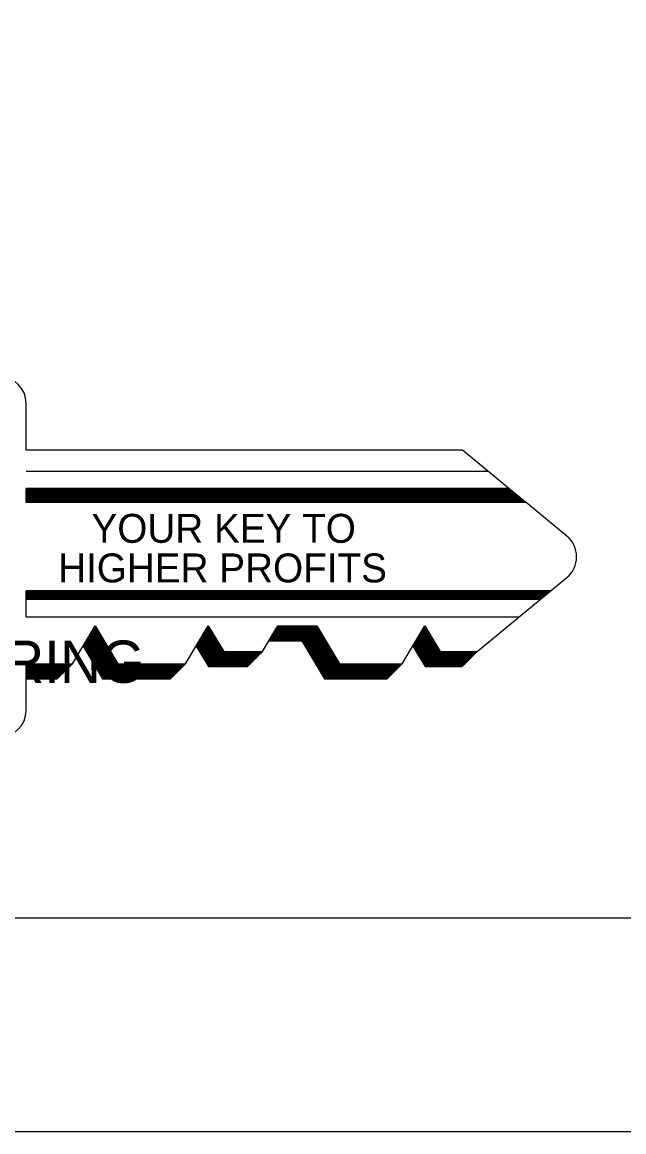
# Model space of a CAD drawing. Extents: x 4.9 to 31.6, y 3.9 to 22.6.
# Drawn here: x 6.8 to 7.739, y 3.926 to 5.658 of the extents above; entities that cross this region are included whole.
import ezdxf

# ---------------------------------------------------------------- set-up
doc = ezdxf.new("R2010")
doc.units = 0
doc.layers.add('Level 1', color=7, linetype='Continuous')

msp = doc.modelspace()

# ---------------------------------------------------------------- linework, layer by layer
at = {"layer": 'Level 1'}
for p, q in [((6.8065, 4.9899), (6.8065, 5.0628)), ((7.4872, 4.9899), (6.8065, 4.9899)), ((7.5859, 4.9082), (7.4874, 4.9899)), ((7.5275, 4.9565), (6.8065, 4.9565)), ((6.8065, 4.908), (6.8065, 4.9297)), ((7.5599, 4.9297), (6.8065, 4.9297)), ((7.5606, 4.9292), (6.8065, 4.9292)), ((7.5612, 4.9287), (6.8065, 4.9287)), ((7.5619, 4.9281), (6.8065, 4.9281)), ((7.5626, 4.9275), (6.8065, 4.9275)), ((7.5633, 4.927), (6.8065, 4.927)), ((7.5641, 4.9263), (6.8065, 4.9263)), ((7.5648, 4.9257), (6.8065, 4.9257)), ((7.5656, 4.925), (6.8065, 4.925)), ((7.5664, 4.9244), (6.8065, 4.9244)), ((7.5671, 4.9238), (6.8065, 4.9238)), ((7.5679, 4.9231), (6.8065, 4.9231)), ((7.5688, 4.9225), (6.8065, 4.9225)), ((7.5694, 4.9219), (6.8065, 4.9219)), ((7.5701, 4.9213), (6.8065, 4.9213)), ((7.5709, 4.9206), (6.8065, 4.9206)), ((7.5718, 4.92), (6.8065, 4.92)), ((7.5725, 4.9193), (6.8065, 4.9193)), ((7.5734, 4.9185), (6.8065, 4.9185)), ((7.5742, 4.918), (6.8065, 4.918)), ((7.5677, 4.9233), (7.5674, 4.9235)), ((7.5681, 4.923), (7.5677, 4.9233)), ((7.5707, 4.9208), (7.5681, 4.923)), ((7.5719, 4.9199), (7.5707, 4.9208)), ((7.5749, 4.9173), (6.8065, 4.9173)), ((7.5759, 4.9165), (6.8065, 4.9165)), ((7.5767, 4.9159), (6.8065, 4.9159)), ((7.5773, 4.9154), (6.8065, 4.9154)), ((7.5781, 4.9147), (6.8065, 4.9147)), ((7.5789, 4.914), (6.8065, 4.914)), ((7.5796, 4.9135), (6.8065, 4.9135)), ((7.5803, 4.9129), (6.8065, 4.9129)), ((7.5809, 4.9124), (6.8065, 4.9124)), ((7.5819, 4.9116), (6.8065, 4.9116)), ((7.5824, 4.9111), (6.8065, 4.9111)), ((7.5831, 4.9105), (6.8065, 4.9105)), ((7.5837, 4.91), (6.8065, 4.91)), ((7.5844, 4.9095), (6.8065, 4.9095)), ((7.5849, 4.9091), (6.8065, 4.9091)), ((7.5854, 4.9086), (6.8065, 4.9086)), ((7.5859, 4.9083), (6.8065, 4.9083)), ((7.5863, 4.908), (6.8065, 4.908)), ((7.5863, 4.908), (7.5859, 4.9082)), ((7.65, 4.8553), (7.5863, 4.908)), ((7.5102, 4.6755), (7.65, 4.7911)), ((7.6249, 4.7703), (6.8065, 4.7703)), ((6.8065, 4.729), (6.8065, 4.7703)), ((7.6235, 4.7692), (6.8065, 4.7692)), ((7.6221, 4.768), (6.8065, 4.768)), ((7.6205, 4.7667), (6.8065, 4.7667)), ((7.6192, 4.7656), (6.8065, 4.7656)), ((7.6176, 4.7643), (6.8065, 4.7643)), ((7.6162, 4.7631), (6.8065, 4.7631)), ((7.6147, 4.7619), (6.8065, 4.7619)), ((7.613, 4.7605), (6.8065, 4.7605)), ((7.6115, 4.7593), (6.8065, 4.7593)), ((7.6101, 4.7581), (6.8065, 4.7581)), ((7.6091, 4.7573), (6.8065, 4.7573)), ((7.6082, 4.7565), (6.8065, 4.7565)), ((7.5749, 4.729), (6.8065, 4.729)), ((6.8788, 4.6565), (6.9142, 4.7156)), ((6.9109, 4.7101), (6.9174, 4.7101)), ((6.9113, 4.7108), (6.9171, 4.7108)), ((6.9117, 4.7115), (6.9167, 4.7115)), ((6.9121, 4.7121), (6.9163, 4.7121)), ((6.9125, 4.7128), (6.9159, 4.7128)), ((6.9129, 4.7135), (6.9155, 4.7135)), ((6.9133, 4.7141), (6.9151, 4.7141)), ((6.9137, 4.7148), (6.9147, 4.7148)), ((6.9142, 4.7156), (6.9495, 4.6565)), ((7.0554, 4.6565), (7.0907, 4.7156)), ((7.0874, 4.7101), (7.0939, 4.7101)), ((7.0878, 4.7108), (7.0936, 4.7108)), ((7.0882, 4.7115), (7.0932, 4.7115)), ((7.0886, 4.7121), (7.0928, 4.7121)), ((7.089, 4.7128), (7.0924, 4.7128)), ((7.0894, 4.7135), (7.092, 4.7135)), ((7.0897, 4.714), (7.0917, 4.714)), ((7.09, 4.7145), (7.0914, 4.7145)), ((7.0903, 4.715), (7.0911, 4.715)), ((7.0907, 4.7156), (7.1148, 4.6755)), ((7.1754, 4.6755), (7.1994, 4.7156)), ((7.1961, 4.7101), (7.2634, 4.7101)), ((7.1965, 4.7108), (7.263, 4.7108)), ((7.1969, 4.7115), (7.2626, 4.7115)), ((7.1974, 4.7121), (7.2622, 4.7121)), ((7.1978, 4.7128), (7.2618, 4.7128)), ((7.1981, 4.7134), (7.2614, 4.7134)), ((7.1984, 4.714), (7.2611, 4.714)), ((7.1988, 4.7145), (7.2608, 4.7145)), ((7.1991, 4.715), (7.2604, 4.715)), ((7.1994, 4.7156), (7.2601, 4.7156)), ((7.2601, 4.7156), (7.2955, 4.6565)), ((7.3932, 4.6565), (7.4286, 4.7156)), ((7.4253, 4.7101), (7.4319, 4.7101)), ((7.4257, 4.7108), (7.4315, 4.7108)), ((7.4261, 4.7115), (7.4311, 4.7115)), ((7.4265, 4.7121), (7.4307, 4.7121)), ((7.4269, 4.7128), (7.4303, 4.7128)), ((7.4273, 4.7135), (7.4299, 4.7135)), ((7.4276, 4.714), (7.4296, 4.714)), ((7.4286, 4.7156), (7.4526, 4.6755)), ((6.9006, 4.6928), (6.9279, 4.6928)), ((6.901, 4.6935), (6.9274, 4.6935)), ((6.9014, 4.6941), (6.927, 4.6941)), ((6.9019, 4.6948), (6.9267, 4.6948)), ((6.9021, 4.6955), (6.9263, 4.6955)), ((6.9025, 4.6961), (6.9259, 4.6961)), ((6.9029, 4.6968), (6.9254, 4.6968)), ((6.9033, 4.6975), (6.925, 4.6975)), ((6.9037, 4.6981), (6.9247, 4.6981)), ((6.9041, 4.6988), (6.9243, 4.6988)), ((6.9045, 4.6995), (6.9239, 4.6995)), ((6.9049, 4.7001), (6.9234, 4.7001)), ((6.9053, 4.7008), (6.923, 4.7008)), ((6.9057, 4.7015), (6.9227, 4.7015)), ((6.9061, 4.7021), (6.9223, 4.7021)), ((6.9065, 4.7028), (6.9219, 4.7028)), ((6.9069, 4.7035), (6.9214, 4.7035)), ((6.9074, 4.7041), (6.9211, 4.7041)), ((6.9078, 4.7048), (6.9207, 4.7048)), ((6.9082, 4.7055), (6.9203, 4.7055)), ((6.9086, 4.7061), (6.9199, 4.7061)), ((6.9089, 4.7068), (6.9194, 4.7068)), ((6.9093, 4.7075), (6.9191, 4.7075)), ((6.9097, 4.7081), (6.9187, 4.7081)), ((6.9101, 4.7088), (6.9183, 4.7088)), ((6.9105, 4.7095), (6.9179, 4.7095)), ((7.0771, 4.6928), (7.1044, 4.6928)), ((7.0775, 4.6935), (7.1039, 4.6935)), ((7.0779, 4.6941), (7.1035, 4.6941)), ((7.0784, 4.6948), (7.1032, 4.6948)), ((7.0786, 4.6955), (7.1028, 4.6955)), ((7.079, 4.6961), (7.1024, 4.6961)), ((7.0794, 4.6968), (7.1019, 4.6968)), ((7.0798, 4.6975), (7.1015, 4.6975)), ((7.0802, 4.6981), (7.1012, 4.6981)), ((7.0806, 4.6988), (7.1008, 4.6988)), ((7.081, 4.6995), (7.1004, 4.6995)), ((7.0814, 4.7001), (7.0999, 4.7001)), ((7.0818, 4.7008), (7.0995, 4.7008)), ((7.0822, 4.7015), (7.0992, 4.7015)), ((7.0826, 4.7021), (7.0988, 4.7021)), ((7.083, 4.7028), (7.0984, 4.7028)), ((7.0834, 4.7035), (7.0979, 4.7035)), ((7.0839, 4.7041), (7.0976, 4.7041)), ((7.0843, 4.7048), (7.0972, 4.7048)), ((7.0847, 4.7055), (7.0968, 4.7055)), ((7.0851, 4.7061), (7.0964, 4.7061)), ((7.0854, 4.7068), (7.0959, 4.7068)), ((7.0858, 4.7075), (7.0956, 4.7075)), ((7.0862, 4.7081), (7.0952, 4.7081)), ((7.0866, 4.7088), (7.0948, 4.7088)), ((7.087, 4.7095), (7.0944, 4.7095)), ((7.1858, 4.6928), (7.2738, 4.6928)), ((7.1862, 4.6935), (7.2734, 4.6935)), ((7.1866, 4.6941), (7.2729, 4.6941)), ((7.1869, 4.6948), (7.2726, 4.6948)), ((7.1874, 4.6955), (7.2722, 4.6955)), ((7.1878, 4.6961), (7.2718, 4.6961)), ((7.1882, 4.6968), (7.2714, 4.6968)), ((7.1885, 4.6975), (7.2709, 4.6975)), ((7.1889, 4.6981), (7.2706, 4.6981)), ((7.1894, 4.6988), (7.2702, 4.6988)), ((7.1898, 4.6995), (7.2698, 4.6995)), ((7.1902, 4.7001), (7.2694, 4.7001)), ((7.1905, 4.7008), (7.2689, 4.7008)), ((7.1909, 4.7015), (7.2686, 4.7015)), ((7.1914, 4.7021), (7.2682, 4.7021)), ((7.1918, 4.7028), (7.2678, 4.7028)), ((7.1922, 4.7035), (7.2674, 4.7035)), ((7.1925, 4.7041), (7.267, 4.7041)), ((7.1929, 4.7048), (7.2666, 4.7048)), ((7.1934, 4.7055), (7.2662, 4.7055)), ((7.1938, 4.7061), (7.2658, 4.7061)), ((7.1942, 4.7068), (7.2654, 4.7068)), ((7.1945, 4.7075), (7.265, 4.7075)), ((7.1949, 4.7081), (7.2646, 4.7081)), ((7.1954, 4.7088), (7.2642, 4.7088)), ((7.1958, 4.7095), (7.2638, 4.7095)), ((7.415, 4.6928), (7.4423, 4.6928)), ((7.4154, 4.6935), (7.4419, 4.6935)), ((7.4159, 4.6941), (7.4414, 4.6941)), ((7.4163, 4.6948), (7.4411, 4.6948)), ((7.4165, 4.6955), (7.4407, 4.6955)), ((7.4169, 4.6961), (7.4403, 4.6961)), ((7.4174, 4.6968), (7.4399, 4.6968)), ((7.4177, 4.6975), (7.4394, 4.6975)), ((7.4181, 4.6981), (7.4391, 4.6981)), ((7.4185, 4.6988), (7.4387, 4.6988)), ((7.4189, 4.6995), (7.4383, 4.6995)), ((7.4194, 4.7001), (7.4379, 4.7001)), ((7.4197, 4.7008), (7.4374, 4.7008)), ((7.4201, 4.7015), (7.4371, 4.7015)), ((7.4205, 4.7021), (7.4367, 4.7021)), ((7.4209, 4.7028), (7.4363, 4.7028)), ((7.4214, 4.7035), (7.4359, 4.7035)), ((7.4218, 4.7041), (7.4355, 4.7041)), ((7.4222, 4.7048), (7.4351, 4.7048)), ((7.4226, 4.7055), (7.4347, 4.7055)), ((7.423, 4.7061), (7.4343, 4.7061)), ((7.4233, 4.7068), (7.4339, 4.7068)), ((7.4237, 4.7075), (7.4335, 4.7075)), ((7.4241, 4.7081), (7.4331, 4.7081)), ((7.4245, 4.7088), (7.4327, 4.7088)), ((7.4249, 4.7095), (7.4323, 4.7095)), ((6.8954, 4.6841), (6.9259, 4.633)), ((6.8954, 4.6841), (6.933, 4.6841)), ((6.8957, 4.6848), (6.9326, 4.6848)), ((6.8958, 4.6835), (6.9334, 4.6835)), ((6.8961, 4.6855), (6.9322, 4.6855)), ((6.8962, 4.6828), (6.9339, 4.6828)), ((6.8965, 4.6861), (6.9319, 4.6861)), ((6.8965, 4.6821), (6.9342, 4.6821)), ((6.8969, 4.6868), (6.9314, 4.6868)), ((6.8969, 4.6815), (6.9346, 4.6815)), ((6.8973, 4.6875), (6.931, 4.6875)), ((6.8974, 4.6808), (6.9349, 4.6808)), ((6.8977, 4.6881), (6.9306, 4.6881)), ((6.8978, 4.6801), (6.9353, 4.6801)), ((6.8981, 4.6888), (6.9303, 4.6888)), ((6.8981, 4.6795), (6.9357, 4.6795)), ((6.8985, 4.6895), (6.9299, 4.6895)), ((6.8985, 4.6788), (6.9361, 4.6788)), ((6.8989, 4.6901), (6.9294, 4.6901)), ((6.8989, 4.6781), (6.9365, 4.6781)), ((6.8994, 4.6908), (6.929, 4.6908)), ((6.8994, 4.6775), (6.9369, 4.6775)), ((6.8998, 4.6915), (6.9286, 4.6915)), ((6.8998, 4.6768), (6.9374, 4.6768)), ((6.9001, 4.6761), (6.9378, 4.6761)), ((6.9002, 4.6921), (6.9283, 4.6921)), ((6.9005, 4.6755), (6.9382, 4.6755)), ((7.0719, 4.6841), (7.0912, 4.652)), ((7.0719, 4.6841), (7.1095, 4.6841)), ((7.0722, 4.6848), (7.1091, 4.6848)), ((7.0723, 4.6835), (7.1099, 4.6835)), ((7.0726, 4.6855), (7.1087, 4.6855)), ((7.0727, 4.6828), (7.1104, 4.6828)), ((7.073, 4.6861), (7.1084, 4.6861)), ((7.073, 4.6821), (7.1107, 4.6821)), ((7.0734, 4.6868), (7.1079, 4.6868)), ((7.0734, 4.6815), (7.1111, 4.6815)), ((7.0738, 4.6875), (7.1075, 4.6875)), ((7.0739, 4.6808), (7.1114, 4.6808)), ((7.0742, 4.6881), (7.1071, 4.6881)), ((7.0743, 4.6801), (7.1118, 4.6801)), ((7.0746, 4.6888), (7.1068, 4.6888)), ((7.0746, 4.6795), (7.1122, 4.6795)), ((7.075, 4.6895), (7.1064, 4.6895)), ((7.075, 4.6788), (7.1126, 4.6788)), ((7.0754, 4.6901), (7.1059, 4.6901)), ((7.0754, 4.6781), (7.113, 4.6781)), ((7.0759, 4.6908), (7.1055, 4.6908)), ((7.0759, 4.6775), (7.1134, 4.6775)), ((7.0763, 4.6915), (7.1051, 4.6915)), ((7.0763, 4.6768), (7.1139, 4.6768)), ((7.0766, 4.6761), (7.1143, 4.6761)), ((7.0767, 4.6921), (7.1048, 4.6921)), ((7.077, 4.6755), (7.1147, 4.6755)), ((7.1148, 4.6755), (7.1754, 4.6755)), ((7.1519, 4.652), (7.1754, 4.6755)), ((7.1854, 4.6921), (7.2742, 4.6921)), ((7.1854, 4.692), (7.2365, 4.692)), ((7.2365, 4.692), (7.2719, 4.633)), ((7.2369, 4.6915), (7.2745, 4.6915)), ((7.2373, 4.6908), (7.2749, 4.6908)), ((7.2377, 4.6901), (7.2754, 4.6901)), ((7.2381, 4.6895), (7.2758, 4.6895)), ((7.2384, 4.6888), (7.2762, 4.6888)), ((7.2389, 4.6881), (7.2765, 4.6881)), ((7.2393, 4.6875), (7.2769, 4.6875)), ((7.2397, 4.6868), (7.2774, 4.6868)), ((7.2401, 4.6861), (7.2778, 4.6861)), ((7.2404, 4.6855), (7.2781, 4.6855)), ((7.2409, 4.6848), (7.2785, 4.6848)), ((7.2413, 4.6841), (7.2789, 4.6841)), ((7.2417, 4.6835), (7.2794, 4.6835)), ((7.2421, 4.6828), (7.2798, 4.6828)), ((7.2424, 4.6821), (7.2801, 4.6821)), ((7.2429, 4.6815), (7.2805, 4.6815)), ((7.2433, 4.6808), (7.2808, 4.6808)), ((7.2437, 4.6801), (7.2812, 4.6801)), ((7.244, 4.6795), (7.2816, 4.6795)), ((7.2444, 4.6788), (7.282, 4.6788)), ((7.2449, 4.6781), (7.2824, 4.6781)), ((7.2453, 4.6775), (7.2829, 4.6775)), ((7.2457, 4.6768), (7.2833, 4.6768)), ((7.246, 4.6761), (7.2837, 4.6761)), ((7.2464, 4.6755), (7.2841, 4.6755)), ((7.4098, 4.6841), (7.429, 4.652)), ((7.4098, 4.6841), (7.4474, 4.6841)), ((7.4101, 4.6848), (7.447, 4.6848)), ((7.4102, 4.6835), (7.4479, 4.6835)), ((7.4105, 4.6855), (7.4466, 4.6855)), ((7.4106, 4.6828), (7.4483, 4.6828)), ((7.4109, 4.6861), (7.4463, 4.6861)), ((7.4109, 4.6821), (7.4486, 4.6821)), ((7.4114, 4.6868), (7.4459, 4.6868)), ((7.4114, 4.6815), (7.449, 4.6815)), ((7.4117, 4.6875), (7.4454, 4.6875)), ((7.4118, 4.6808), (7.4493, 4.6808)), ((7.4121, 4.6881), (7.445, 4.6881)), ((7.4122, 4.6801), (7.4497, 4.6801)), ((7.4125, 4.6888), (7.4447, 4.6888)), ((7.4125, 4.6795), (7.4501, 4.6795)), ((7.4129, 4.6895), (7.4443, 4.6895)), ((7.4129, 4.6788), (7.4505, 4.6788)), ((7.4134, 4.6901), (7.4439, 4.6901)), ((7.4134, 4.6781), (7.4509, 4.6781)), ((7.4138, 4.6908), (7.4434, 4.6908)), ((7.4138, 4.6775), (7.4514, 4.6775)), ((7.4142, 4.6915), (7.443, 4.6915)), ((7.4142, 4.6768), (7.4518, 4.6768)), ((7.4145, 4.6761), (7.4522, 4.6761)), ((7.4146, 4.6921), (7.4427, 4.6921)), ((7.4149, 4.6755), (7.4526, 4.6755)), ((7.4526, 4.6755), (7.5102, 4.6755)), ((7.4866, 4.652), (7.5102, 4.6755)), ((6.9009, 4.6748), (6.9386, 4.6748)), ((6.9013, 4.6743), (6.9389, 4.6743)), ((6.9016, 4.6736), (6.9393, 4.6736)), ((6.902, 4.673), (6.9397, 4.673)), ((6.9024, 4.6722), (6.9402, 4.6722)), ((6.9029, 4.6714), (6.9407, 4.6714)), ((6.9034, 4.6706), (6.9411, 4.6706)), ((6.9039, 4.6697), (6.9417, 4.6697)), ((6.9044, 4.6689), (6.9421, 4.6689)), ((6.9051, 4.6679), (6.9428, 4.6679)), ((6.9056, 4.667), (6.9433, 4.667)), ((6.9062, 4.666), (6.9439, 4.666)), ((6.9068, 4.665), (6.9445, 4.665)), ((6.9073, 4.6641), (6.945, 4.6641)), ((6.9078, 4.6633), (6.9455, 4.6633)), ((6.9084, 4.6623), (6.9461, 4.6623)), ((6.9089, 4.6614), (6.9466, 4.6614)), ((6.9095, 4.6604), (6.9472, 4.6604)), ((6.9104, 4.659), (6.948, 4.659)), ((6.911, 4.658), (6.9487, 4.658)), ((7.0774, 4.6748), (7.1151, 4.6748)), ((7.0778, 4.6743), (7.1154, 4.6743)), ((7.0781, 4.6736), (7.1158, 4.6736)), ((7.0785, 4.673), (7.1162, 4.673)), ((7.0789, 4.6722), (7.1167, 4.6722)), ((7.0794, 4.6714), (7.1172, 4.6714)), ((7.0799, 4.6706), (7.1176, 4.6706)), ((7.0802, 4.6703), (7.1702, 4.6703)), ((7.0808, 4.6693), (7.1692, 4.6693)), ((7.0814, 4.6683), (7.1682, 4.6683)), ((7.0819, 4.6674), (7.1673, 4.6674)), ((7.0825, 4.6664), (7.1663, 4.6664)), ((7.0831, 4.6654), (7.1653, 4.6654)), ((7.0837, 4.6644), (7.1643, 4.6644)), ((7.0844, 4.6634), (7.1633, 4.6634)), ((7.0847, 4.6627), (7.1626, 4.6627)), ((7.0852, 4.662), (7.1619, 4.662)), ((7.0858, 4.661), (7.1609, 4.661)), ((7.0864, 4.66), (7.1599, 4.66)), ((7.0869, 4.6591), (7.159, 4.6591)), ((7.0875, 4.658), (7.1579, 4.658)), ((7.1032, 4.6747), (7.1746, 4.6747)), ((7.1032, 4.674), (7.1739, 4.674)), ((7.1032, 4.6732), (7.1731, 4.6732)), ((7.1032, 4.6723), (7.1722, 4.6723)), ((7.1032, 4.6714), (7.1713, 4.6714)), ((7.2469, 4.6748), (7.2845, 4.6748)), ((7.2472, 4.6743), (7.2849, 4.6743)), ((7.2475, 4.6736), (7.2852, 4.6736)), ((7.2479, 4.673), (7.2856, 4.673)), ((7.2484, 4.6722), (7.2861, 4.6722)), ((7.2489, 4.6714), (7.2866, 4.6714)), ((7.2494, 4.6706), (7.287, 4.6706)), ((7.2499, 4.6697), (7.2876, 4.6697)), ((7.2504, 4.6689), (7.288, 4.6689)), ((7.251, 4.6679), (7.2887, 4.6679)), ((7.2515, 4.667), (7.2892, 4.667)), ((7.2521, 4.666), (7.2898, 4.666)), ((7.2527, 4.665), (7.2904, 4.665)), ((7.2532, 4.6641), (7.2909, 4.6641)), ((7.2537, 4.6633), (7.2914, 4.6633)), ((7.2544, 4.6623), (7.292, 4.6623)), ((7.2549, 4.6614), (7.2925, 4.6614)), ((7.2554, 4.6604), (7.2931, 4.6604)), ((7.2563, 4.659), (7.2939, 4.659)), ((7.2569, 4.658), (7.2946, 4.658)), ((7.4154, 4.6748), (7.453, 4.6748)), ((7.4157, 4.6743), (7.4534, 4.6743)), ((7.416, 4.6736), (7.4537, 4.6736)), ((7.4164, 4.673), (7.4541, 4.673)), ((7.4169, 4.6722), (7.4546, 4.6722)), ((7.4174, 4.6714), (7.4551, 4.6714)), ((7.4179, 4.6706), (7.4555, 4.6706)), ((7.4181, 4.6703), (7.5049, 4.6703)), ((7.4187, 4.6693), (7.5039, 4.6693)), ((7.4193, 4.6683), (7.5029, 4.6683)), ((7.4199, 4.6674), (7.502, 4.6674)), ((7.4204, 4.6664), (7.501, 4.6664)), ((7.421, 4.6654), (7.5, 4.6654)), ((7.4216, 4.6644), (7.499, 4.6644)), ((7.4223, 4.6634), (7.498, 4.6634)), ((7.4226, 4.6627), (7.4974, 4.6627)), ((7.4231, 4.662), (7.4966, 4.662)), ((7.4237, 4.661), (7.4956, 4.661)), ((7.4243, 4.66), (7.4946, 4.66)), ((7.4248, 4.6591), (7.4938, 4.6591)), ((7.4254, 4.658), (7.4927, 4.658)), ((7.4411, 4.6747), (7.5094, 4.6747)), ((7.4411, 4.674), (7.5086, 4.674)), ((7.4411, 4.6732), (7.5079, 4.6732)), ((7.4411, 4.6723), (7.5069, 4.6723)), ((7.4411, 4.6714), (7.506, 4.6714)), ((6.8065, 4.5836), (6.8065, 4.6565)), ((6.8065, 4.6565), (6.8788, 4.6565)), ((6.8065, 4.6557), (6.8779, 4.6557)), ((6.8065, 4.655), (6.8772, 4.655)), ((6.8065, 4.6542), (6.8764, 4.6542)), ((6.8065, 4.6533), (6.8755, 4.6533)), ((6.8065, 4.6524), (6.8746, 4.6524)), ((6.8065, 4.6513), (6.8735, 4.6513)), ((6.8065, 4.6503), (6.8725, 4.6503)), ((6.8065, 4.6493), (6.8715, 4.6493)), ((6.8065, 4.6484), (6.8706, 4.6484)), ((6.8065, 4.6474), (6.8696, 4.6474)), ((6.8065, 4.6464), (6.8686, 4.6464)), ((6.8065, 4.6454), (6.8676, 4.6454)), ((6.8065, 4.6444), (6.8666, 4.6444)), ((6.8065, 4.6437), (6.8659, 4.6437)), ((6.8065, 4.643), (6.8652, 4.643)), ((6.8065, 4.642), (6.8642, 4.642)), ((6.8065, 4.641), (6.8632, 4.641)), ((6.8552, 4.633), (6.8788, 4.6565)), ((6.9117, 4.6568), (6.9494, 4.6568)), ((6.9124, 4.6557), (7.0545, 4.6557)), ((6.9128, 4.655), (7.0538, 4.655)), ((6.9133, 4.6542), (7.053, 4.6542)), ((6.9138, 4.6533), (7.0521, 4.6533)), ((6.9144, 4.6524), (7.0512, 4.6524)), ((6.915, 4.6513), (7.0501, 4.6513)), ((6.9156, 4.6503), (7.0491, 4.6503)), ((6.9162, 4.6493), (7.0481, 4.6493)), ((6.9167, 4.6484), (7.0472, 4.6484)), ((6.9174, 4.6474), (7.0462, 4.6474)), ((6.9179, 4.6464), (7.0452, 4.6464)), ((6.9185, 4.6454), (7.0442, 4.6454)), ((6.9191, 4.6444), (7.0432, 4.6444)), ((6.9195, 4.6437), (7.0425, 4.6437)), ((6.9199, 4.643), (7.0418, 4.643)), ((6.9205, 4.642), (7.0408, 4.642)), ((6.9212, 4.641), (7.0398, 4.641)), ((6.9495, 4.6565), (7.0554, 4.6565)), ((7.0318, 4.633), (7.0554, 4.6565)), ((7.0881, 4.657), (7.1569, 4.657)), ((7.0888, 4.656), (7.1559, 4.656)), ((7.0893, 4.6551), (7.155, 4.6551)), ((7.09, 4.654), (7.1539, 4.654)), ((7.0906, 4.653), (7.1529, 4.653)), ((7.0912, 4.652), (7.1519, 4.652)), ((7.2576, 4.6568), (7.2953, 4.6568)), ((7.2583, 4.6557), (7.3924, 4.6557)), ((7.2587, 4.655), (7.3916, 4.655)), ((7.2592, 4.6542), (7.3909, 4.6542)), ((7.2597, 4.6533), (7.3899, 4.6533)), ((7.2603, 4.6524), (7.389, 4.6524)), ((7.2609, 4.6513), (7.3879, 4.6513)), ((7.2615, 4.6503), (7.3869, 4.6503)), ((7.2621, 4.6493), (7.3859, 4.6493)), ((7.2626, 4.6484), (7.385, 4.6484)), ((7.2633, 4.6474), (7.384, 4.6474)), ((7.2639, 4.6464), (7.383, 4.6464)), ((7.2644, 4.6454), (7.382, 4.6454)), ((7.265, 4.6444), (7.381, 4.6444)), ((7.2654, 4.6437), (7.3804, 4.6437)), ((7.2659, 4.643), (7.3796, 4.643)), ((7.2664, 4.642), (7.3786, 4.642)), ((7.2671, 4.641), (7.3776, 4.641)), ((7.2955, 4.6565), (7.3932, 4.6565)), ((7.3696, 4.633), (7.3932, 4.6565)), ((7.426, 4.657), (7.4917, 4.657)), ((7.4267, 4.656), (7.4907, 4.656)), ((7.4272, 4.6551), (7.4898, 4.6551)), ((7.4279, 4.654), (7.4886, 4.654)), ((7.4285, 4.653), (7.4876, 4.653)), ((7.429, 4.652), (7.4866, 4.652)), ((6.8065, 4.6401), (6.8624, 4.6401)), ((6.8065, 4.639), (6.8613, 4.639)), ((6.8065, 4.638), (6.8603, 4.638)), ((6.8065, 4.637), (6.8593, 4.637)), ((6.8065, 4.6361), (6.8584, 4.6361)), ((6.8065, 4.635), (6.8572, 4.635)), ((6.8065, 4.634), (6.8562, 4.634)), ((6.8065, 4.633), (6.8552, 4.633)), ((6.9217, 4.6401), (7.0389, 4.6401)), ((6.9223, 4.639), (7.0379, 4.639)), ((6.9229, 4.638), (7.0369, 4.638)), ((6.9235, 4.637), (7.0359, 4.637)), ((6.924, 4.6361), (7.0349, 4.6361)), ((6.9248, 4.635), (7.0338, 4.635)), ((6.9254, 4.634), (7.0328, 4.634)), ((6.9259, 4.633), (7.0318, 4.633)), ((7.2676, 4.6401), (7.3768, 4.6401)), ((7.2682, 4.639), (7.3757, 4.639)), ((7.2689, 4.638), (7.3747, 4.638)), ((7.2694, 4.637), (7.3737, 4.637)), ((7.2699, 4.6361), (7.3728, 4.6361)), ((7.2707, 4.635), (7.3716, 4.635)), ((7.2713, 4.634), (7.3706, 4.634)), ((7.2719, 4.633), (7.3696, 4.633))]:
    msp.add_line(p, q, dxfattribs=at)
for points in [[(4.9069, 22.5927), (31.5735, 22.5927), (31.5735, 3.926), (4.9069, 3.926)], [(5.9069, 22.2594), (31.2402, 22.2594), (31.2402, 4.2594), (5.9069, 4.2594)]]:
    msp.add_lwpolyline(points, close=True, dxfattribs=at)
for centre, start, end in [((6.7649, 5.0628), 0, 90), ((7.6235, 4.8232), 309.5794, 50.3991), ((6.7649, 4.5836), 270, 0)]:
    msp.add_arc(centre, 0.0417, start, end, dxfattribs=at)

# ---------------------------------------------------------------- texts
for s, height, p in [('YOUR KEY TO', 0.045125, (6.9085, 4.8452)), ('HIGHER PROFITS', 0.045125, (6.8564, 4.7834)), ('ENGINEERING', 0.065995, (6.3739, 4.6266))]:
    msp.add_text(s, height=height, dxfattribs=at).set_placement(p)

doc.saveas('drawing.dxf')
